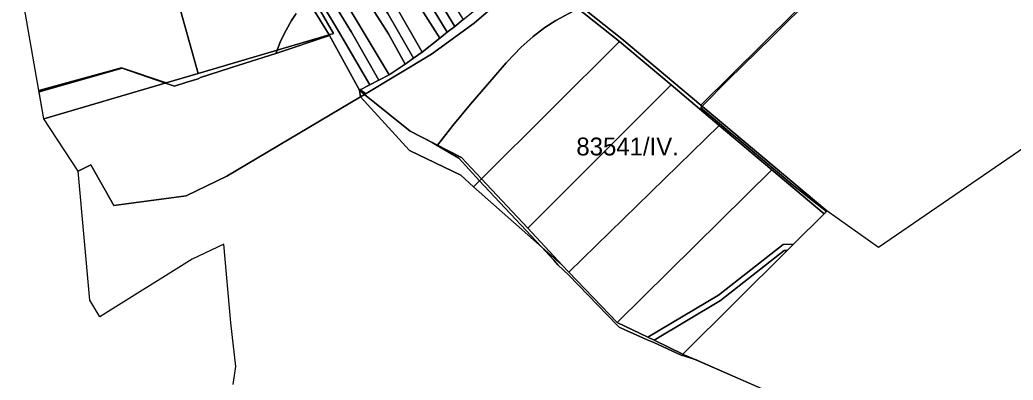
# Model space of a CAD drawing. Extents: x -521939 to -516426, y -1197857 to -1189551.
# Drawn here: x -518655 to -517823, y -1197101 to -1196799 of the extents above; entities that cross this region are included whole.
import ezdxf

# ---------------------------------------------------------------- set-up
doc = ezdxf.new("R2010")
doc.units = 0
for name, color, linetype in [('95560013', 7, 'Continuous'), ('95610013', 7, 'Continuous'), ('95620013', 7, 'Continuous'), ('95640013', 7, 'Continuous'), ('95660013', 7, 'Continuous')]:
    doc.layers.add(name, color=color, linetype=linetype)

msp = doc.modelspace()

# ---------------------------------------------------------------- linework, layer by layer
at = {"layer": '95560013'}
msp.add_lwpolyline([(-518154.91, -1197052.53), (-518195.2, -1197010.55), (-518069.43, -1196887.51), (-518025.21, -1196924.74)], close=True, dxfattribs=at)
at = {"layer": '95610013'}
for points in [[(-518569.85, -1196839.17), (-518639.16, -1196858.36), (-518654.2, -1196771.74), (-518655.02, -1196705.87), (-518633.55, -1196638.3), (-518635.54, -1196625.44), (-518630.52, -1196628.95), (-518618.09, -1196630.78), (-518607.94, -1196642.28), (-518552.13, -1196666.23), (-518522.09, -1196785.01), (-518505.67, -1196843.94), (-518532.46, -1196851.82)], [(-518395.91, -1196811.65), (-518505.67, -1196843.94), (-518522.09, -1196785.01), (-518552.13, -1196666.23), (-518474.2, -1196699.66), (-518439.92, -1196736.28), (-518432.09, -1196753.01)], [(-518447.03, -1196722.37), (-518472.61, -1196661.14), (-518461.08, -1196662.79), (-518455.47, -1196679.63), (-518442.82, -1196710.62), (-518422.87, -1196750.78), (-518388.29, -1196808.61), (-518361.9, -1196853.51), (-518370.59, -1196857.92), (-518395.91, -1196811.65), (-518392.31, -1196810.59), (-518438.02, -1196731.62)], [(-518455.47, -1196679.63), (-518461.08, -1196662.79), (-518451.52, -1196664.16), (-518447.46, -1196677.1), (-518414.82, -1196748.23), (-518377.45, -1196809.33), (-518354.33, -1196849.66), (-518361.9, -1196853.51), (-518388.29, -1196808.61), (-518422.87, -1196750.78), (-518442.82, -1196710.62)], [(-518447.46, -1196677.1), (-518451.52, -1196664.16), (-518443.06, -1196665.37), (-518439.85, -1196673.35), (-518424.97, -1196706.38), (-518406.23, -1196746.06), (-518375.88, -1196794.93), (-518345.67, -1196845.27), (-518354.33, -1196849.66), (-518377.45, -1196809.33), (-518414.82, -1196748.23)], [(-518345.67, -1196845.27), (-518375.88, -1196794.93), (-518406.23, -1196746.06), (-518424.97, -1196706.38), (-518439.85, -1196673.35), (-518443.06, -1196665.37), (-518422.2, -1196668.36), (-518407.8, -1196704.44), (-518387, -1196745.69), (-518369.23, -1196774.61), (-518346.25, -1196810.78), (-518332.39, -1196836.06)], [(-518290.9, -1196804.55), (-518312.84, -1196768.4), (-518338.72, -1196728), (-518361.09, -1196687.71), (-518365.83, -1196676.42), (-518364.1, -1196659.07), (-518355.05, -1196680.82), (-518331.59, -1196723.52), (-518314.62, -1196750.17), (-518283.76, -1196798.87)], [(-518346.25, -1196810.78), (-518369.23, -1196774.61), (-518387, -1196745.69), (-518407.8, -1196704.44), (-518422.2, -1196668.36), (-518412.63, -1196669.73), (-518401.03, -1196696.58), (-518383.01, -1196734.44), (-518361.61, -1196771.22), (-518346.98, -1196793.72), (-518325.36, -1196831.19), (-518332.39, -1196836.06)], [(-518401.03, -1196696.58), (-518412.63, -1196669.73), (-518403.42, -1196671.05), (-518393.83, -1196693.42), (-518373.94, -1196733.11), (-518352.82, -1196768.94), (-518339.12, -1196789.49), (-518318.13, -1196826.18), (-518325.36, -1196831.19), (-518346.98, -1196793.72), (-518361.61, -1196771.22), (-518383.01, -1196734.44)], [(-518318.13, -1196826.18), (-518339.12, -1196789.49), (-518352.82, -1196768.94), (-518373.94, -1196733.11), (-518393.83, -1196693.42), (-518403.42, -1196671.05), (-518384.01, -1196673.82), (-518379.18, -1196685.71), (-518356.93, -1196729.74), (-518303.28, -1196814.38)], [(-518303.28, -1196814.38), (-518356.93, -1196729.74), (-518379.18, -1196685.71), (-518384.01, -1196673.82), (-518374.74, -1196675.15), (-518372.06, -1196681.97), (-518352.02, -1196720.38), (-518337.63, -1196743), (-518312.84, -1196783.64), (-518297.15, -1196809.51)], [(-518337.63, -1196743), (-518352.02, -1196720.38), (-518372.06, -1196681.97), (-518374.74, -1196675.15), (-518365.83, -1196676.42), (-518361.09, -1196687.71), (-518338.72, -1196728), (-518312.84, -1196768.4), (-518290.9, -1196804.55), (-518297.15, -1196809.51), (-518312.84, -1196783.64)], [(-518285.15, -1196914.46), (-518328.32, -1196892.23), (-518366.35, -1196861.67), (-518310.33, -1196827.79), (-518274.56, -1196801.96), (-518225.47, -1196759.41), (-518152.89, -1196817.24), (-518268.42, -1196932.35)], [(-518229.79, -1196973.69), (-518268.42, -1196932.35), (-518152.89, -1196817.24), (-518109.7, -1196853.6)], [(-518195.2, -1197010.55), (-518200.83, -1197004.68), (-518229.79, -1196973.69), (-518109.7, -1196853.6), (-518069.43, -1196887.51)], [(-518069.99, -1197029.8), (-518129.22, -1197064.94), (-518154.91, -1197052.53), (-518025.21, -1196924.74), (-517981.57, -1196961.49), (-518007.29, -1196987.05), (-518015.82, -1196987.24)], [(-518099.9, -1197079.1), (-518123.76, -1197067.57), (-518068.23, -1197034.23), (-518015.04, -1196992.27), (-518012.54, -1196992.27)]]:
    msp.add_lwpolyline(points, close=True, dxfattribs=at)
msp.add_lwpolyline([(-517980.47, -1196766.88), (-518084.82, -1196870.43), (-518150.89, -1196815.02), (-518223.57, -1196757.13)], dxfattribs=at)
at = {"layer": '95620013'}
for points in [[(-517813.49, -1196905.82), (-517935.92, -1196989.92), (-517979.14, -1196959.07), (-518084.82, -1196870.43), (-517980.47, -1196766.88), (-517876.11, -1196663.33), (-517940.75, -1196585.61), (-517939.19, -1196584.82), (-517930.62, -1196580.45), (-517920.51, -1196575.3), (-517905.03, -1196569.49), (-517886.45, -1196560.09), (-517883.07, -1196560.46), (-517789.59, -1196404.25)], [(-518476.45, -1197104.51), (-518474.25, -1197089.5), (-518478.28, -1197052.83), (-518484.35, -1196987.06), (-518510.74, -1196999.5), (-518588, -1197047.91), (-518596.53, -1197033.9), (-518606.26, -1196925.9), (-518595.7, -1196920.42), (-518576.23, -1196954.72), (-518515.71, -1196946.46), (-518481.64, -1196930.16), (-518369.69, -1196863.69), (-518328.64, -1196908.57), (-518285.89, -1196929.32), (-518275.03, -1196938.94), (-518200.83, -1197004.68), (-518195.2, -1197010.55), (-518154.91, -1197052.53), (-518129.22, -1197064.94), (-518123.76, -1197067.57), (-518099.9, -1197079.1), (-517998.84, -1197123.4)]]:
    msp.add_lwpolyline(points, dxfattribs=at)
msp.add_lwpolyline([(-518369.69, -1196863.69), (-518481.64, -1196930.16), (-518515.71, -1196946.46), (-518576.23, -1196954.72), (-518595.7, -1196920.42), (-518606.26, -1196925.9), (-518635.06, -1196882), (-518532.46, -1196851.82), (-518505.67, -1196843.94), (-518395.91, -1196811.65), (-518370.59, -1196857.92)], close=True, dxfattribs=at)
at = {"layer": '95640013'}
for points in [[(-518447.03, -1196722.37), (-518438.02, -1196731.62), (-518392.31, -1196810.59), (-518395.91, -1196811.65), (-518432.09, -1196753.01), (-518439.92, -1196736.28)], [(-518366.35, -1196861.67), (-518370.59, -1196857.92), (-518361.9, -1196853.51), (-518354.33, -1196849.66), (-518345.67, -1196845.27), (-518332.39, -1196836.06), (-518325.36, -1196831.19), (-518318.13, -1196826.18), (-518303.28, -1196814.38), (-518297.15, -1196809.51), (-518290.9, -1196804.55), (-518283.76, -1196798.87), (-518275.61, -1196792.4), (-518268.19, -1196786.5), (-518258.73, -1196780.27), (-518249.81, -1196774.4), (-518243.27, -1196768.33), (-518234.82, -1196760.49), (-518228.44, -1196752.68), (-518223.57, -1196757.13), (-518225.47, -1196759.41), (-518274.56, -1196801.96), (-518310.33, -1196827.79)], [(-518152.89, -1196817.24), (-518225.47, -1196759.41), (-518223.57, -1196757.13), (-518150.89, -1196815.02), (-518084.82, -1196870.43), (-517979.14, -1196959.07), (-517981.57, -1196961.49), (-518025.21, -1196924.74), (-518069.43, -1196887.51), (-518109.7, -1196853.6)], [(-518532.46, -1196851.82), (-518635.06, -1196882), (-518639.16, -1196858.36), (-518569.85, -1196839.17)], [(-518369.69, -1196863.69), (-518370.59, -1196857.92), (-518366.35, -1196861.67)], [(-518285.89, -1196929.32), (-518328.64, -1196908.57), (-518369.69, -1196863.69), (-518366.35, -1196861.67), (-518328.32, -1196892.23), (-518285.15, -1196914.46), (-518268.42, -1196932.35), (-518275.03, -1196938.94)], [(-518200.83, -1197004.68), (-518275.03, -1196938.94), (-518268.42, -1196932.35), (-518229.79, -1196973.69)], [(-518123.76, -1197067.57), (-518129.22, -1197064.94), (-518069.99, -1197029.8), (-518015.82, -1196987.24), (-518007.29, -1196987.05), (-518012.54, -1196992.27), (-518015.04, -1196992.27), (-518068.23, -1197034.23)]]:
    msp.add_lwpolyline(points, close=True, dxfattribs=at)
at = {"layer": '95660013'}
for points in [[(-518423.72, -1196793.78), (-518427.43, -1196799.69), (-518432.07, -1196807.69), (-518436.7, -1196816.96), (-518439.68, -1196824.53), (-518440.7, -1196827.13), (-518471.71, -1196837.04), (-518503.88, -1196847.33), (-518505.67, -1196848.46), (-518515.11, -1196851.33), (-518525.58, -1196854.51), (-518533, -1196851.98), (-518569.28, -1196839.62), (-518614.4, -1196852.31), (-518638.99, -1196859.35), (-518639.16, -1196858.36), (-518654.2, -1196771.74)], [(-517813.49, -1196905.82), (-517935.92, -1196989.92), (-517979.14, -1196959.07), (-517979.66, -1196959.59), (-518008.38, -1196936.91), (-518045.42, -1196905.84), (-518054.46, -1196898.26), (-518061.26, -1196892.54), (-518069.25, -1196885.83), (-518084.83, -1196872.75), (-518083.57, -1196871.48), (-518061.53, -1196849.11), (-518025.83, -1196814.22), (-517989.32, -1196777.42)], [(-517989.32, -1196777.42), (-518025.83, -1196814.22), (-518061.53, -1196849.11), (-518083.57, -1196871.48), (-518084.83, -1196872.75), (-518069.25, -1196885.83), (-518061.26, -1196892.54), (-518054.46, -1196898.26), (-518045.42, -1196905.84), (-518008.38, -1196936.91), (-517979.66, -1196959.59)], [(-518187.59, -1196789.59), (-518206.22, -1196799.51), (-518215.55, -1196805.48), (-518225.17, -1196812.9), (-518235.48, -1196822.29), (-518246.84, -1196834.11), (-518247.73, -1196835.13), (-518259.84, -1196849.1), (-518277.79, -1196869.81), (-518292.51, -1196887.55), (-518305.37, -1196904.05), (-518305.55, -1196904.28), (-518309.89, -1196901.72), (-518328.32, -1196892.23), (-518366.35, -1196861.67), (-518365.38, -1196861.08), (-518369.48, -1196857.85), (-518369.69, -1196857.46), (-518370.59, -1196857.92), (-518395.63, -1196812.16), (-518440.7, -1196827.13), (-518439.68, -1196824.53), (-518436.7, -1196816.96), (-518432.07, -1196807.69), (-518427.43, -1196799.69), (-518423.72, -1196793.78)], [(-517979.66, -1196959.59), (-517981.57, -1196961.49), (-518007.29, -1196987.05), (-518012.54, -1196992.27), (-518099.9, -1197079.1), (-518087.9, -1197084.36), (-518099.97, -1197080.34), (-518100.07, -1197080.44), (-518101.15, -1197079.95), (-518124.11, -1197069.56), (-518126.83, -1197068.38), (-518129.67, -1197067.15), (-518141.38, -1197061.85), (-518145.79, -1197059.87), (-518153.11, -1197056.58), (-518155.08, -1197054.66), (-518195.39, -1197012.96), (-518204.43, -1197004.42), (-518208, -1197000.47), (-518215.14, -1196992.56), (-518218.17, -1196989.32), (-518223.11, -1196984.03), (-518231.08, -1196975.5), (-518266.23, -1196938.26), (-518270.1, -1196934.02), (-518287.53, -1196914.93), (-518305.55, -1196904.28), (-518305.37, -1196904.05), (-518292.51, -1196887.55), (-518277.79, -1196869.81), (-518259.84, -1196849.1), (-518247.73, -1196835.13), (-518246.84, -1196834.11), (-518235.48, -1196822.29), (-518225.17, -1196812.9), (-518215.55, -1196805.48), (-518206.22, -1196799.51), (-518187.59, -1196789.59)], [(-518476.45, -1197104.51), (-518474.25, -1197089.5), (-518478.28, -1197052.83), (-518484.35, -1196987.06), (-518510.74, -1196999.5), (-518588, -1197047.91), (-518596.53, -1197033.9), (-518606.26, -1196925.9), (-518635.06, -1196882), (-518638.99, -1196859.35), (-518614.4, -1196852.31), (-518569.28, -1196839.62), (-518533, -1196851.98), (-518525.58, -1196854.51), (-518515.11, -1196851.33), (-518505.67, -1196848.46), (-518503.88, -1196847.33), (-518471.71, -1196837.04), (-518440.7, -1196827.13), (-518395.63, -1196812.16), (-518370.59, -1196857.92), (-518369.69, -1196857.46), (-518369.48, -1196857.85), (-518365.38, -1196861.08), (-518366.35, -1196861.67), (-518328.32, -1196892.23), (-518309.89, -1196901.72), (-518305.55, -1196904.28), (-518287.53, -1196914.93), (-518270.1, -1196934.02), (-518266.23, -1196938.26), (-518231.08, -1196975.5), (-518223.11, -1196984.03), (-518218.17, -1196989.32), (-518215.14, -1196992.56), (-518208, -1197000.47), (-518204.43, -1197004.42), (-518195.39, -1197012.96), (-518155.08, -1197054.66), (-518153.11, -1197056.58), (-518145.79, -1197059.87), (-518141.38, -1197061.85), (-518129.67, -1197067.15), (-518126.83, -1197068.38), (-518124.11, -1197069.56), (-518101.15, -1197079.95), (-518100.07, -1197080.44), (-518099.97, -1197080.34), (-518087.9, -1197084.36), (-517998.84, -1197123.4)]]:
    msp.add_lwpolyline(points, dxfattribs=at)

# ---------------------------------------------------------------- texts
msp.add_text('83541/IV.', height=15, rotation=360, dxfattribs=at).set_placement((-518189.02, -1196912.69))

doc.saveas('drawing.dxf')
